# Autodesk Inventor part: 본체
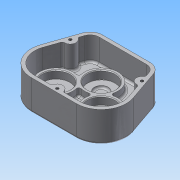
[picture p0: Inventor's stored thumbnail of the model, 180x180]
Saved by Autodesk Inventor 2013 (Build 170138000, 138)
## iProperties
Created: 2014-12
Part Number: 본체
Material: 알루미늄 6061
Document SubType Name: Modeling
Designer: Administrator
Density: 2.71 g/cm^3
Mass: 596.952 g
Surface Area: 670.328 cm^2
Volume: 220.278 cm^3
Author: Administrator
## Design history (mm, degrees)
sketch "스케치1"
  geometry: L1 (-32.527, -68.527)-(32.527, -68.527); L2 (-67.006, -22.085)-(-47, 36); L3 (-47, 36)-(47, 36); L4 (47, 36)-(67.006, -22.085); L5 (-32.527, -32.527)-(0, 0); L6 (0, 0)-(32.527, -32.527); A1 r 36 centre (-32.527, -32.527) between (-66.565, -20.803) and (-32.527, -68.527); A2 r 36 centre (32.527, -32.527) between (32.527, -68.527) and (66.565, -20.803); 1 further point
  constraints: 12 end point, 4 point on circle, 3 tangent, 2 centre point, 2 coincident, 2 point on line, 1 equal length, 1 horizontal, 1 horizontal alignment, 1 midpoint, 1 parallel, 1 vertical alignment
  dimensions: "d4" = 36 distance of L5.end point (0, 36); "d5" = 94 distance of L2.end L3.end; "d6" = 46 distance of L5.end L5.start; "d7" = 46 distance of L5.end L6.end; "d72" = 90 deg angle of L6 L5; "d73" = 72 diameter of A1; "d75" = 36 radius of A2
extrude "돌출1" new body sketch "스케치1" distance "d8" = 44; taper "d9" = 0 deg
fillet "모깎기1" dims "d13" = 18
sketch "스케치15"
  geometry: L1 (34.162, 36)-(-34.162, 36) reference; L2 (-51.181, 23.862)-(-66.565, -20.803) reference; L3 (-32.527, -68.527)-(32.527, -68.527) reference; L4 (66.565, -20.803)-(51.181, 23.862) reference; L5 (-34.162, 31)-(34.162, 31); L6 (46.453, 22.233)-(61.837, -22.432); L7 (32.527, -63.527)-(-32.527, -63.527); L8 (-61.837, -22.432)-(-46.453, 22.233); A1 r 18 centre (34.162, 18) between (51.181, 23.862) and (34.162, 36) reference; A2 r 18 centre (-34.162, 18) between (-34.162, 36) and (-51.181, 23.862) reference; A3 r 36 centre (-32.527, -32.527) between (-66.565, -20.803) and (-32.527, -68.527) reference; A4 r 36 centre (32.527, -32.527) between (32.527, -68.527) and (66.565, -20.803) reference; A5 r 13 centre (34.162, 18) between (46.453, 22.233) and (34.162, 31); A6 r 31 centre (32.527, -32.527) between (32.527, -63.527) and (61.837, -22.432); A7 r 31 centre (-32.527, -32.527) between (-61.837, -22.432) and (-32.527, -63.527); A8 r 13 centre (-34.162, 18) between (-34.162, 31) and (-46.453, 22.233); 1 further point
  constraints: 8 end point, 8 point on circle, 4 centre point, 7 other
  dimensions: "d76" = 5 distance between parallel lines of L1 L5
extrude "돌출12" cut sketch "스케치15" distance "d77" = 34; taper "d78" = 0 deg
sketch "스케치16"
  geometry: C1 r 24 at (0, 0); C2 r 24 at (-32.527, -32.527); C3 r 24 at (32.527, -32.527); A1 r 31 centre (-32.527, -32.527) between (-61.837, -22.432) and (-32.527, -63.527) reference; A2 r 31 centre (32.527, -32.527) between (32.527, -63.527) and (61.837, -22.432) reference; 1 further point
  constraints: 3 centre point, 3 coincident
  dimensions: "d79" = 48 diameter of C1; "d80" = 48 diameter of C2; "d81" = 48 diameter of C3
extrude "돌출13" join sketch "스케치16" distance "d82" = 11; taper "d83" = 0 deg
sketch "스케치17"
  geometry: C1 r 20 at (0, 0); A1 r 24 centre (0, 0) between (21.111, -11.416) and (-21.111, -11.416) reference
  constraints: 1 centre point, 1 coincident
  dimensions: "d84" = 40 diameter of C1
extrude "돌출14" cut sketch "스케치17" distance "d85" = 12; taper "d86" = 0 deg
sketch "스케치18"
  geometry: C1 r 20 at (-32.527, -32.527); C2 r 20 at (32.527, -32.527); A1 r 24 centre (32.527, -32.527) between (11.416, -21.111) and (21.111, -11.416) reference; A2 r 24 centre (-32.527, -32.527) between (-21.111, -11.416) and (-11.416, -21.111) reference
  constraints: 2 centre point, 2 coincident
  dimensions: "d87" = 40 diameter of C1; "d88" = 40 diameter of C2
extrude "돌출15" cut sketch "스케치18" distance "d89" = 11; taper "d90" = 0 deg
sketch "스케치19"
  geometry: C1 r 20 at (-32.527, -32.527); C2 r 20 at (32.527, -32.527); A1 r 36 centre (-32.527, -32.527) between (-66.565, -20.803) and (-32.527, -68.527) reference; A2 r 36 centre (32.527, -32.527) between (32.527, -68.527) and (66.565, -20.803) reference; 1 further point
  constraints: 2 centre point, 2 coincident
  dimensions: "d91" = 40 diameter of C1; "d92" = 40 diameter of C2
extrude "돌출16" join sketch "스케치19" distance "d93" = 7; taper "d94" = -10 deg
sketch "스케치20"
  geometry: C1 r 18.766 at (0, 0) reference; C2 r 18.766 at (65.054, 0) reference; 3 further points
  constraints: 2 coincident
hole "구멍2" sketch "스케치20" at (0, 0), (65.054, 0) diameter "d95" = 15.5; stored, may be unused: countersink angle "d99" = 90 deg, drill point angle "d101" = 118 deg; dims "d96" = 6, "d97" = 30, "d98" = 7, "d100" = 8
sketch "스케치21"
  geometry: C1 r 20 at (0, 0) reference; C2 r 10 at (0, 0)
  constraints: 1 centre point, 1 coincident
  dimensions: "d102" = 20 diameter of C2
extrude "돌출17" cut sketch "스케치21" distance "d103" = 3; taper "d104" = 0 deg
sketch "스케치22"
  geometry: L1 (-34.162, 36)-(34.162, 36) reference; 2 further points
  constraints: 1 vertical alignment, 1 other
  dimensions: "d105" = 30 distance from line of L1 point (0, 6)
feature "엠보싱2" sketch "스케치22" dims "d4" = 36, "d5" = 94, "d6" = 46, "d7" = 46, "d72" = 90 deg, "d73" = 72, "d75" = 36, "d106" = 1, "d107" = 0
sketch "스케치23"
  geometry: L1 (46.453, 22.233)-(61.837, -22.432) reference; L2 (32.527, -63.527)-(-32.527, -63.527) reference; L3 (-61.837, -22.432)-(-46.453, 22.233) reference; L4 (34.162, 36)-(-34.162, 36) reference; A1 r 8 centre (-51.7, 7) between (-54.305, -0.564) and (-49.095, 14.564); A2 r 8 centre (51.7, 7) between (49.095, 14.564) and (54.305, -0.564); A3 r 8 centre (0, -63.527) between (8, -63.527) and (-8, -63.527); 1 further point
  constraints: 8 point on line, 6 point on circle, 3 centre point, 1 horizontal alignment, 1 midpoint
  dimensions: "d108" = 16 diameter of A1; "d109" = 16 diameter of A2; "d110" = 16 diameter of A3; "d111" = 29 distance from line of L4 A1.centre
extrude "돌출18" join sketch "스케치23" stored distance "d112" = 3; taper "d113" = 0 deg
sketch "스케치24"
  geometry: A1 r 8 centre (0, -63.527) between (8, -63.527) and (-8, -63.527) reference; A2 r 8 centre (-51.7, 7) between (-54.305, -0.564) and (-49.095, 14.564) reference; A3 r 8 centre (51.7, 7) between (49.095, 14.564) and (54.305, -0.564) reference; 4 further points
  constraints: 3 coincident
hole "구멍3" sketch "스케치24" at (-51.7, 7), (0, -63.527), (51.7, 7) diameter "d114" = 4.134; stored, may be unused: countersink angle "d118" = 90 deg, drill point angle "d120" = 118 deg; dims "d115" = 13, "d116" = 30, "d117" = 7, "d119" = 20
fillet "모깎기5" dims "d121" = 3
fillet "모깎기6" dims "d122" = 3
fillet "모깎기7" dims "d123" = 3
fillet "모깎기8" dims "d124" = 3
fillet "모깎기9" dims "d125" = 3
fillet "모깎기10" dims "d126" = 0.3
fillet "모깎기11" dims "d127" = 3
fillet "모깎기12" dims "d128" = 0.3
fillet "모깎기13" dims "d129" = 3
chamfer "모따기2" distance "d130" = 1; stored, may be unused: second distance "d131" = 2, angle "d132" = 45 deg
node "솔리드1"
node "투영된 루프3"
other parameters: "d74" = 72
